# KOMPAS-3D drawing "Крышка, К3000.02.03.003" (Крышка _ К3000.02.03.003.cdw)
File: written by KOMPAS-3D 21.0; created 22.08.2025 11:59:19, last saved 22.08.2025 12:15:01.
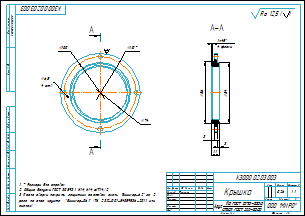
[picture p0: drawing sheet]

Sheet 1: A3, landscape

Document properties: Автор: Lutik; Знак неуказанной шероховатости: 4; Параметр неуказанной шероховатости: Ra 12,5; Масса: 0.259809

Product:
- Part/product: Крышка  | designation К3000.02.03.003
    Материал: Круг$d110 ГОСТ 2590-2006;Ст3сп ГОСТ 535-2005$ (density 7850 kg/m3)
    Масса: 0.259809
    Форматы листов документа: A3
  - Body: Тело 1
      Масса: 0.271427

Title block, sheet 1: Наименование: Крышка; designation: К3000.02.03.003; Материал: Круг 110 ГОСТ 2590-2006 Ст3сп ГОСТ 535-2005; Масса: 0,26; Количество листов документа: 1; organisation: ООО "МИРО"; Форматы листов документа: A3; stored path: C:\Users\Lutik\YandexDisk\Документы\Новая папка\Бабка задняя\2D\Опора_К3000.02.03.000\Крышка _ К3000.02.03.003.cdw; Разработал: Тимонин

Views: Вид 1, Спереди, Разрез А-А
Referenced files in C:\Users\Lutik\YandexDisk\Документы\Новая папка\Бабка задняя\3D\: Крышка.m3d
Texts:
  Ra 12,5
  Ra 12,5 ( )
  К3000.02.03.003 Крышка
Dimensions and other numbers on the sheet: 100; 6,5; 4 отв.; 110; 74; 84; 11; 3; 1; 4 фаски; 86; 1:1; 0,26

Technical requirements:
  * Размеры для справок.
  Общие допуски ГОСТ 30893.1: H14, h14, ±IT14/2.
  После сварки покрыть защитным составом эмаль "Виникор-62" за 2
  раза по слою грунта  "Виникор-061" (ТУ 2312-001-54359536-2011 или
  аналог).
